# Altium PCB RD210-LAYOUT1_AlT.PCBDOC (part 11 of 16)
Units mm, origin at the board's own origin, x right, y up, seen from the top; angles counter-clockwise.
Board outline 330 x 300 mm, 6 copper layers (TOP, Mid-Layer 1, Mid-Layer 2, Mid-Layer 3, Mid-Layer 4, BOTTOM), stack 1.422 mm thick; 981 components, 463 nets, 2326 pads, 12534 vias.
Unrouted connection lines stored in the file: 6.
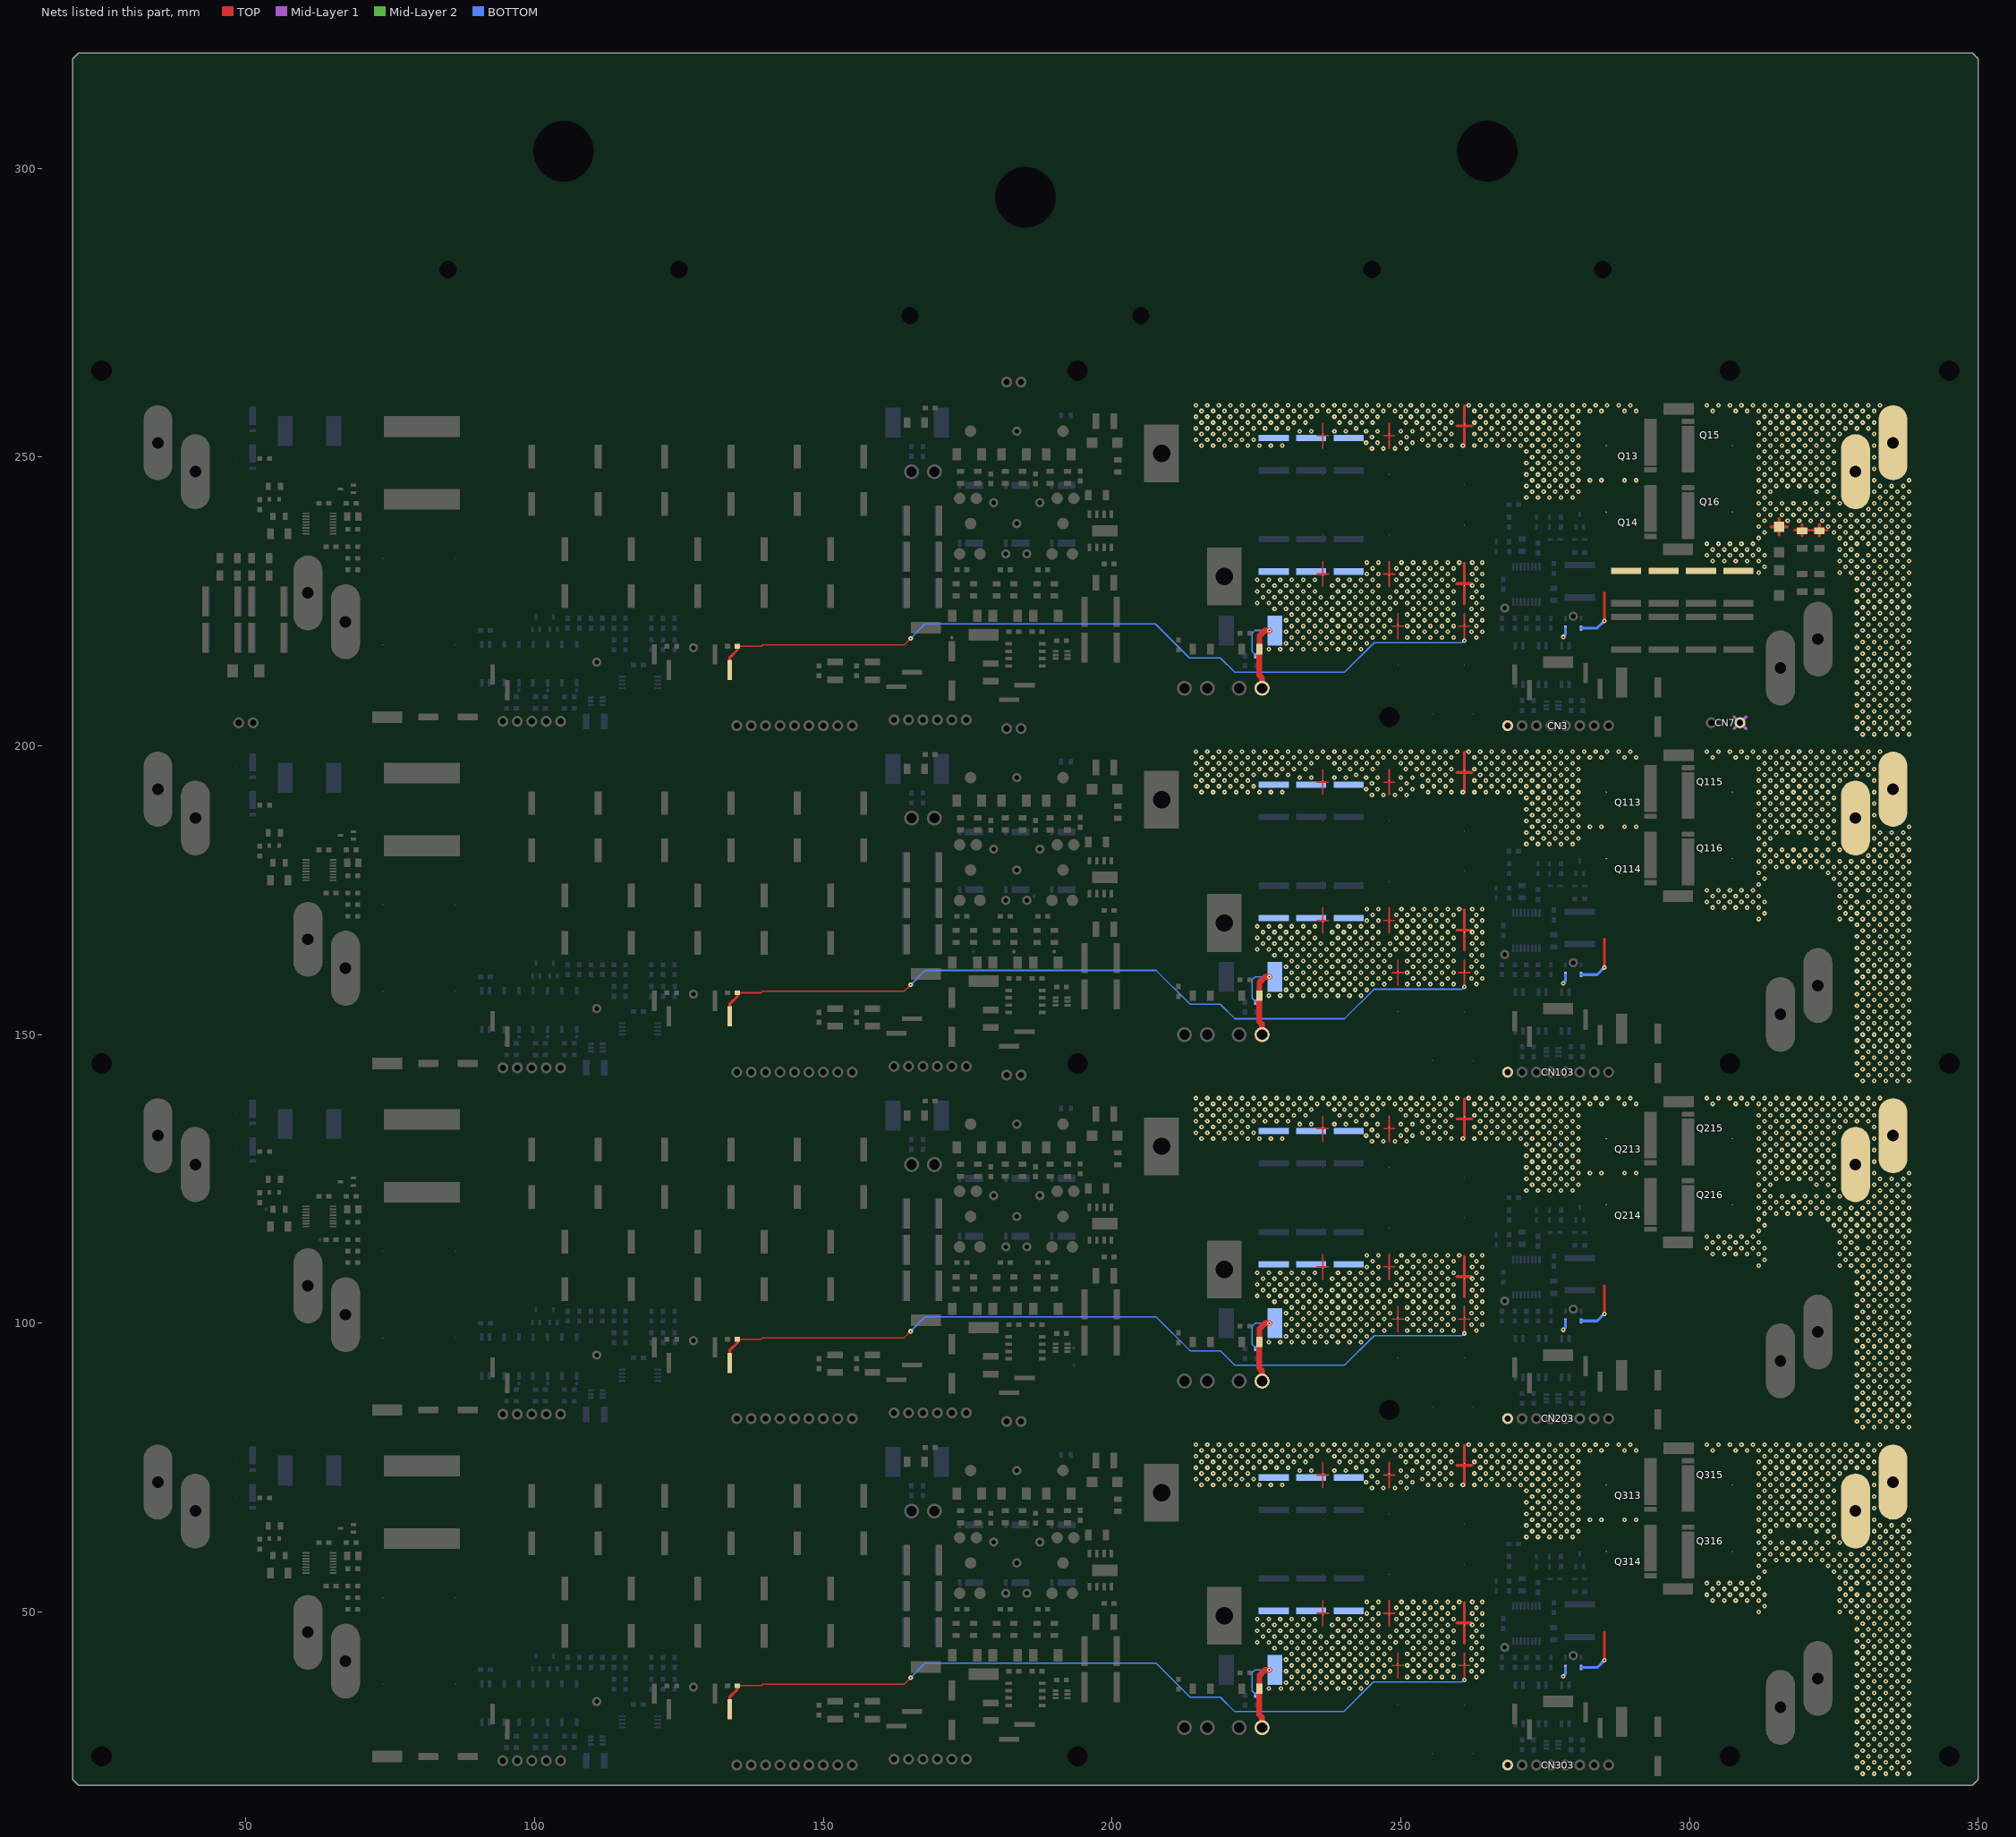
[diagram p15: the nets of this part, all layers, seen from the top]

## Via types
v1: diameter 0.8, hole 0.3, TOP to BOTTOM, 12534 vias

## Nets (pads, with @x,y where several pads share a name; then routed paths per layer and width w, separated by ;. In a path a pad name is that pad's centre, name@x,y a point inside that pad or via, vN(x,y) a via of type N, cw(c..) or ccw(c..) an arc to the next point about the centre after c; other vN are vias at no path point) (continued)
VP_L: C85.2 C87.2 C89.2 C91.2 C93.2 C95.2 CN7.1 D13.1 D15.1 D113.1 D213.1 D313.1 Q15.3 Q16.3 Q115.3 Q116.3 Q215.3 Q216.3 Q315.3 Q316.3 TN13.1 TN13.2 TN23.1 TN23.2 TN33.1 TN33.2 TN43.1 TN43.2 | length 63.9
  TOP w0.5: v1(285.25,41.625) 285.25,46.5 ; v1(285.25,101.625) 285.25,106.5 ; v1(285.25,161.625) 285.25,166.5 ; v1(285.25,221.625) 285.25,226.5 ; 314.1,237.95 D15.1@315.5,237.95 ; 315.5,236.55 D15.1@315.5,237.95 ; 315.5,239.35 D15.1@315.5,237.95 ; 316.9,237.95 D15.1@315.5,237.95 ; 318.2,237.35 C85.2@319.5,237.35 ; 319.5,236.35 C85.2@319.5,237.275 C85.2@319.5,237.35 ; 319.5,238.35 C85.2@319.5,237.35 ; 320.8,237.35 C85.2@319.5,237.35 ; 321.2,237.35 C87.2@322.5,237.35 ; 322.5,236.35 C87.2@322.5,237.275 C87.2@322.5,237.35 ; 322.5,238.35 C87.2@322.5,237.35 ; 323.8,237.35 C87.2@322.5,237.35
  Mid-Layer 1 w0.5: 307.725,202.975 CN7.1@308.75,204 ; 307.725,205.025 CN7.1@308.75,204 ; 309.775,202.975 CN7.1@308.75,204 ; 309.775,205.025 CN7.1@308.75,204
  Mid-Layer 2 w0.5: 307.725,202.975 CN7.1@308.75,204 ; 307.725,205.025 CN7.1@308.75,204 ; 309.775,202.975 CN7.1@308.75,204 ; 309.775,205.025 CN7.1@308.75,204
  BOTTOM w0.5: D313.1@281.25,40.4 284.025,40.4 v1(285.25,41.625) ; D213.1@281.25,100.4 284.025,100.4 v1(285.25,101.625) ; D113.1@281.25,160.4 284.025,160.4 v1(285.25,161.625) ; D13.1@281.25,220.4 284.025,220.4 v1(285.25,221.625)
  other v1: 330,22 332,22 334,22 336,22 338,22 329,23 331,23 333,23 335,23 337,23 330,24 332,24 334,24 336,24 338,24 329,25 331,25 333,25 335,25 337,25 330,26 332,26 334,26 336,26 338,26 329,27 331,27 333,27 335,27 337,27 330,28 332,28 334,28 336,28 338,28 329,29 331,29 333,29 335,29 337,29 330,30 332,30 334,30 336,30 338,30 329,31 331,31 333,31 335,31 337,31 330,32 332,32 334,32 336,32 338,32 329,33 331,33 333,33 335,33 337,33 330,34 332,34 334,34 336,34 338,34 329,35 331,35 333,35 335,35 337,35 330,36 332,36 334,36 336,36 338,36 329,37 331,37 333,37 335,37 337,37 330,38 332,38 334,38 336,38 338,38 329,39 331,39 333,39 335,39 337,39 330,40 332,40 334,40 336,40 338,40 329,41 331,41 333,41 335,41 337,41 330,42 332,42 334,42 336,42 338,42 329,43 331,43 333,43 335,43 337,43 330,44 332,44 334,44 336,44 338,44 329,45 331,45 333,45 335,45 337,45 330,46 332,46 334,46 336,46 338,46 329,47 331,47 333,47 335,47 337,47 330,48 332,48 334,48 336,48 338,48 329,49 331,49 333,49 335,49 337,49 312,50 326,50 328,50 330,50 332,50 334,50 336,50 338,50 313,51 327,51 329,51 331,51 333,51 335,51 337,51 304,52 306,52 308,52 310,52 312,52 326,52 328,52 330,52 332,52 334,52 336,52 338,52 303,53 305,53 307,53 309,53 311,53 313,53 327,53 329,53 331,53 333,53 335,53 337,53 304,54 306,54 308,54 310,54 312,54 326,54 328,54 332,54 334,54 336,54 338,54 303,55 305,55 307,55 309,55 311,55 327,55 329,55 331,55 333,55 335,55 337,55 312,56 326,56 328,56 330,56 332,56 334,56 336,56 338,56 313,57 325,57 327,57 329,57 331,57 333,57 335,57 337,57 312,58 324,58 326,58 328,58 330,58 332,58 334,58 336,58 338,58 313,59 315,59 317,59 319,59 321,59 323,59 325,59 327,59 329,59 331,59 333,59 335,59 337,59 312,60 314,60 316,60 318,60 320,60 322,60 324,60 326,60 328,60 330,60 332,60 334,60 336,60 338,60 313,61 315,61 317,61 319,61 321,61 323,61 331,61 333,61 335,61 337,61 312,62 314,62 316,62 318,62 320,62 322,62 324,62 326,62 332,62 334,62 336,62 338,62 313,63 325,63 333,63 335,63 337,63 312,64 314,64 322,64 324,64 332,64 334,64 336,64 338,64 313,65 315,65 317,65 319,65 321,65 323,65 325,65 333,65 335,65 337,65 312,66 314,66 316,66 318,66 320,66 322,66 324,66 332,66 338,66 313,67 315,67 317,67 319,67 321,67 323,67 325,67 312,68 314,68 316,68 318,68 320,68 322,68 324,68 332,68 313,69 315,69 317,69 319,69 321,69 323,69 325,69 312,70 314,70 316,70 318,70 320,70 322,70 324,70 332,70 313,71 315,71 317,71 319,71 321,71 323,71 325,71 312,72 314,72 316,72 318,72 320,72 322,72 324,72 332,72 313,73 315,73 317,73 319,73 321,73 323,73 325,73 312,74 314,74 316,74 318,74 320,74 322,74 324,74 326,74 332,74 313,75 315,75 317,75 319,75 321,75 323,75 325,75 327,75 329,75 331,75 312,76 314,76 316,76 318,76 320,76 322,76 324,76 326,76 328,76 330,76 332,76 313,77 315,77 317,77 319,77 321,77 323,77 325,77 327,77 329,77 331,77 304,78 308,78 310,78 312,78 314,78 316,78 318,78 320,78 322,78 324,78 326,78 328,78 330,78 332,78 303,79 305,79 307,79 309,79 311,79 313,79 315,79 317,79 319,79 321,79 323,79 325,79 327,79 329,79 331,79 333,79 330,82 332,82 334,82 336,82 338,82 329,83 331,83 333,83 335,83 337,83 330,84 332,84 334,84 336,84 338,84 329,85 331,85 333,85 335,85 337,85 330,86 332,86 334,86 336,86 338,86 329,87 331,87 333,87 335,87 337,87 330,88 332,88 334,88 336,88 338,88 329,89 331,89 333,89 335,89 337,89 330,90 332,90 334,90 336,90 338,90 329,91 331,91 333,91 335,91 337,91 330,92 332,92 334,92 336,92 338,92 329,93 331,93 333,93 335,93 337,93 330,94 332,94 334,94 336,94 338,94 329,95 331,95 333,95 335,95 337,95 330,96 332,96 334,96 336,96 338,96 329,97 331,97 333,97 335,97 337,97 330,98 332,98 334,98 336,98 338,98 329,99 331,99 333,99 335,99 337,99 330,100 332,100 334,100 336,100 338,100 329,101 331,101 333,101 335,101 337,101 330,102 332,102 334,102 336,102 338,102 329,103 331,103 333,103 335,103 337,103 330,104 332,104 334,104 336,104 338,104 329,105 331,105 333,105 335,105 337,105 330,106 332,106 334,106 336,106 338,106 329,107 331,107 333,107 335,107 337,107 330,108 332,108 334,108 336,108 338,108 329,109 331,109 333,109 335,109 337,109 312,110 326,110 328,110 330,110 332,110 334,110 336,110 338,110 313,111 327,111 329,111 331,111 333,111 335,111 337,111 304,112 306,112 308,112 310,112 312,112 326,112 328,112 330,112 332,112 334,112 336,112 338,112 303,113 305,113 307,113 309,113 311,113 313,113 327,113 329,113 331,113 333,113 335,113 337,113 304,114 306,114 308,114 310,114 312,114 326,114 328,114 332,114 334,114 336,114 338,114 303,115 305,115 307,115 309,115 311,115 327,115 329,115 331,115 333,115 335,115 337,115 312,116 326,116 328,116 330,116 332,116 334,116 336,116 338,116 313,117 325,117 327,117 329,117 331,117 333,117 335,117 337,117 312,118 324,118 326,118 328,118 330,118 332,118 334,118 336,118 338,118 313,119 315,119 317,119 319,119 321,119 323,119 325,119 327,119 329,119 331,119 333,119 335,119 337,119 312,120 314,120 316,120 318,120 320,120 322,120 324,120 326,120 328,120 330,120 332,120 334,120 336,120 338,120 313,121 315,121 317,121 319,121 321,121 323,121 331,121 333,121 335,121 337,121 312,122 314,122 316,122 318,122 320,122 322,122 324,122 326,122 332,122 334,122 336,122 338,122 313,123 325,123 333,123 335,123 337,123 312,124 314,124 322,124 324,124 332,124 334,124 336,124 338,124 313,125 315,125 317,125 319,125 321,125 323,125 325,125 333,125 335,125 337,125 312,126 314,126 316,126 318,126 320,126 322,126 324,126 332,126 338,126 313,127 315,127 317,127 319,127 321,127 323,127 325,127 312,128 314,128 316,128 318,128 320,128 322,128 324,128 332,128 313,129 315,129 317,129 319,129 321,129 323,129 325,129 312,130 314,130 316,130 318,130 320,130 322,130 324,130 332,130 313,131 315,131 317,131 319,131 321,131 323,131 325,131 312,132 314,132 316,132 318,132 320,132 322,132 324,132 332,132 313,133 315,133 317,133 319,133 321,133 323,133 325,133 312,134 314,134 316,134 318,134 320,134 322,134 324,134 326,134 332,134 313,135 315,135 317,135 319,135 321,135 323,135 325,135 327,135 329,135 331,135 312,136 314,136 316,136 318,136 320,136 322,136 324,136 326,136 328,136 330,136 332,136 313,137 315,137 317,137 319,137 321,137 323,137 325,137 327,137 329,137 331,137 304,138 308,138 310,138 312,138 314,138 316,138 318,138 320,138 322,138 324,138 326,138 328,138 330,138 332,138 303,139 305,139 307,139 309,139 311,139 313,139 315,139 317,139 319,139 321,139 323,139 325,139 327,139 329,139 331,139 333,139 330,142 332,142 334,142 336,142 338,142 329,143 331,143 333,143 335,143 337,143 330,144 332,144 334,144 336,144 338,144 329,145 331,145 333,145 335,145 337,145 330,146 332,146 334,146 336,146 338,146 329,147 331,147 333,147 335,147 337,147 330,148 332,148 334,148 336,148 338,148 329,149 331,149 333,149 335,149 337,149 330,150 332,150 334,150 336,150 338,150 329,151 331,151 333,151 335,151 337,151 330,152 332,152 334,152 336,152 338,152 329,153 331,153 333,153 335,153 337,153 330,154 332,154 334,154 336,154 338,154 329,155 331,155 333,155 335,155 337,155 330,156 332,156 334,156 336,156 338,156 329,157 331,157 333,157 335,157 337,157 330,158 332,158 334,158 336,158 338,158 329,159 331,159 333,159 335,159 337,159 330,160 332,160 334,160 336,160 338,160 329,161 331,161 333,161 335,161 337,161 330,162 332,162 334,162 336,162 338,162 329,163 331,163 333,163 335,163 337,163 330,164 332,164 334,164 336,164 338,164 329,165 331,165 333,165 335,165 337,165 330,166 332,166 334,166 336,166 338,166 329,167 331,167 333,167 335,167 337,167 330,168 332,168 334,168 336,168 338,168 329,169 331,169 333,169 335,169 337,169 312,170 326,170 328,170 330,170 332,170 334,170 336,170 338,170 313,171 327,171 329,171 331,171 333,171 335,171 337,171 304,172 306,172 308,172 310,172 312,172 326,172 328,172 330,172 332,172 334,172 336,172 338,172 303,173 305,173 307,173 309,173 311,173 313,173 327,173 329,173 331,173 333,173 335,173 337,173 304,174 306,174 308,174 310,174 312,174 326,174 328,174 332,174 334,174 336,174 338,174 303,175 305,175 307,175 309,175 311,175 327,175 329,175 331,175 333,175 335,175 337,175 312,176 326,176 328,176 330,176 332,176 334,176 336,176 338,176 313,177 325,177 327,177 329,177 331,177 333,177 335,177 337,177 312,178 324,178 326,178 328,178 330,178 332,178 334,178 336,178 338,178 313,179 315,179 317,179 319,179 321,179 323,179 325,179 327,179 329,179 331,179 333,179 335,179 337,179 312,180 314,180 316,180 318,180 320,180 322,180 324,180 326,180 328,180 330,180 332,180 334,180 336,180 338,180 313,181 315,181 317,181 319,181 321,181 323,181 331,181 333,181 335,181 337,181 312,182 314,182 316,182 318,182 320,182 322,182 324,182 326,182 332,182 334,182 336,182 338,182 313,183 325,183 333,183 335,183 337,183 312,184 314,184 322,184 324,184 332,184 334,184 336,184 338,184 313,185 315,185 317,185 319,185 321,185 323,185 325,185 333,185 335,185 337,185 312,186 314,186 316,186 318,186 320,186 322,186 324,186 332,186 338,186 313,187 315,187 317,187 319,187 321,187 323,187 325,187 312,188 314,188 316,188 318,188 320,188 322,188 324,188 332,188 313,189 315,189 317,189 319,189 321,189 323,189 325,189 312,190 314,190 316,190 318,190 320,190 322,190 324,190 332,190 313,191 315,191 317,191 319,191 321,191 323,191 325,191 312,192 314,192 316,192 318,192 320,192 322,192 324,192 332,192 313,193 315,193 317,193 319,193 321,193 323,193 325,193 312,194 314,194 316,194 318,194 320,194 322,194 324,194 326,194 332,194 313,195 315,195 317,195 319,195 321,195 323,195 325,195 327,195 329,195 331,195 312,196 314,196 316,196 318,196 320,196 322,196 324,196 326,196 328,196 330,196 332,196 313,197 315,197 317,197 319,197 321,197 323,197 325,197 327,197 329,197 331,197 304,198 308,198 310,198 312,198 314,198 316,198 318,198 320,198 322,198 324,198 326,198 328,198 330,198 332,198 303,199 305,199 307,199 309,199 311,199 313,199 315,199 317,199 319,199 321,199 323,199 325,199 327,199 329,199 331,199 333,199 330,202 332,202 334,202 336,202 338,202 329,203 331,203 333,203 335,203 337,203 330,204 332,204 334,204 336,204 338,204 329,205 331,205 333,205 335,205 337,205 330,206 332,206 334,206 336,206 338,206 329,207 331,207 333,207 335,207 337,207 330,208 332,208 334,208 336,208 338,208 329,209 331,209 333,209 335,209 337,209 330,210 332,210 334,210 336,210 338,210 329,211 331,211 333,211 335,211 337,211 330,212 332,212 334,212 336,212 338,212 329,213 331,213 333,213 335,213 337,213 330,214 332,214 334,214 336,214 338,214 329,215 331,215 333,215 335,215 337,215 330,216 332,216 334,216 336,216 338,216 329,217 331,217 333,217 335,217 337,217 330,218 332,218 334,218 336,218 338,218 329,219 331,219 333,219 335,219 337,219 330,220 332,220 334,220 336,220 338,220 329,221 331,221 333,221 335,221 337,221 330,222 332,222 334,222 336,222 338,222 329,223 331,223 333,223 335,223 337,223 330,224 332,224 334,224 336,224 338,224 329,225 331,225 333,225 335,225 337,225 330,226 332,226 334,226 336,226 338,226 329,227 331,227 333,227 335,227 337,227 330,228 332,228 334,228 336,228 338,228 329,229 331,229 333,229 335,229 337,229 312,230 326,230 328,230 330,230 332,230 334,230 336,230 338,230 313,231 327,231 329,231 331,231 333,231 335,231 337,231 304,232 306,232 308,232 310,232 312,232 326,232 328,232 330,232 332,232 334,232 336,232 338,232 303,233 305,233 307,233 309,233 311,233 313,233 327,233 329,233 331,233 333,233 335,233 337,233 304,234 306,234 308,234 310,234 312,234 326,234 328,234 332,234 334,234 336,234 338,234 303,235 305,235 307,235 309,235 311,235 327,235 329,235 331,235 333,235 335,235 337,235 312,236 326,236 328,236 330,236 332,236 334,236 336,236 338,236 313,237 325,237 327,237 329,237 331,237 333,237 335,237 337,237 312,238 324,238 326,238 328,238 330,238 332,238 334,238 336,238 338,238 313,239 317,239 319,239 321,239 323,239 325,239 327,239 329,239 331,239 333,239 335,239 337,239 312,240 314,240 316,240 318,240 320,240 322,240 324,240 326,240 328,240 330,240 332,240 334,240 336,240 338,240 313,241 315,241 317,241 319,241 321,241 323,241 331,241 333,241 335,241 337,241 312,242 314,242 316,242 318,242 320,242 322,242 324,242 326,242 332,242 334,242 336,242 338,242 313,243 325,243 333,243 335,243 337,243 312,244 314,244 322,244 324,244 332,244 334,244 336,244 338,244 313,245 315,245 317,245 319,245 321,245 323,245 325,245 333,245 335,245 337,245 312,246 314,246 316,246 318,246 320,246 322,246 324,246 332,246 338,246 313,247 315,247 317,247 319,247 321,247 323,247 325,247 312,248 314,248 316,248 318,248 320,248 322,248 324,248 332,248 313,249 315,249 317,249 319,249 321,249 323,249 325,249 312,250 314,250 316,250 318,250 320,250 322,250 324,250 332,250 313,251 315,251 317,251 319,251 321,251 323,251 325,251 312,252 314,252 316,252 318,252 320,252 322,252 324,252 332,252 313,253 315,253 317,253 319,253 321,253 323,253 325,253 312,254 314,254 316,254 318,254 320,254 322,254 324,254 326,254 332,254 313,255 315,255 317,255 319,255 321,255 323,255 325,255 327,255 329,255 331,255 312,256 314,256 316,256 318,256 320,256 322,256 324,256 326,256 328,256 330,256 332,256 313,257 315,257 317,257 319,257 321,257 323,257 325,257 327,257 329,257 331,257 304,258 308,258 310,258 312,258 314,258 316,258 318,258 320,258 322,258 324,258 326,258 328,258 330,258 332,258 303,259 305,259 307,259 309,259 311,259 313,259 315,259 317,259 319,259 321,259 323,259 325,259 327,259 329,259 331,259 333,259
VP_L_0-1: C50.1 C51.1 C52.1 C53.1 C54.1 C55.1 C56.1 C57.1 C58.1 C59.2 C60.2 C61.2 C62.2 C63.2 C64.2 C403.2 CN3.8 CN9.1 CN18.1 D12.1 Q13.3 Q14.3 R38.2 R55.2 | length 216
  TOP w0.25: R55.2@135.1,217.25 139.25,217.25 139.5,217.5 164,217.5 v1(165.125,218.625) ; 235.523,229.775 236.5,229.775 ; 235.523,253.725 236.5,253.725 ; 236.5,227.573 C53.1@236.5,229.5 236.5,229.775 ; 236.5,231.977 236.5,229.775 ; 236.5,251.523 236.5,253.725 ; 236.5,255.927 C51.1@236.5,254 236.5,253.725 ; 237.477,229.775 236.5,229.775 ; 237.477,253.725 236.5,253.725 ; 247.023,229.775 248,229.775 ; 247.023,253.725 248,253.725 ; 248,227.573 C54.1@248,229.5 248,229.775 ; 248,231.977 248,229.775 ; 248,251.523 248,253.725 ; 248,255.927 C52.1@248,254 248,253.725 ; 248.523,220.725 249.5,220.725 ; 248.977,229.775 248,229.775 ; 248.977,253.725 248,253.725 ; 249.5,218.523 249.5,220.725 ; 249.5,222.927 C55.1@249.5,221 249.5,220.725 ; 250.477,220.725 249.5,220.725 ; 260.023,220.725 261,220.725 ; v1(261,218.25) 261,220.725 ; 261,222.927 C56.1@261,221 261,220.725 ; 261.977,220.725 261,220.725
  TOP w0.5: CN18.1@133.77,213.15 133.77,215.27 135.1,216.6 R55.2@135.1,217.25 ; 259.696,228.1 261,228.1 ; 259.696,255.4 261,255.4 ; 261,224.596 C58.1@261,227.75 261,228.1 ; 261,231.604 261,228.1 ; v1@261,251.896 261,255.4 ; 261,258.904 C57.1@261,255.75 261,255.4 ; v1@262.304,228.1 261,228.1 ; 262.304,255.4 261,255.4
  TOP w1: CN9.1@225.98,210 225.98,211.77 225.5,212.25 225.5,216.625 225.525,216.65 C403.2@225.525,216.75 225.525,219.025 226.5,220 v1(227.25,220)
  BOTTOM w0.25: v1(165.125,218.625) 167.625,221.125 207.5,221.125 213.375,215.25 218.75,215.25 221.25,212.75 240.25,212.75 245.375,217.875 260.625,217.875 v1(261,218.25) ; C50.1@225,215.6 224.25,216.35 224.25,219.5 224.75,220 v1(227.25,220)
  BOTTOM w0.5: v1(278.125,218.875) 278.5,219.25 D12.1@278.5,220.4
  other v1: 227.125,216.75 229.125,216.75 231.125,216.75 233.125,216.75 235.125,216.75 237.125,216.75 239.125,216.75 241.125,216.75 243.125,216.75 230.125,217.75 232.125,217.75 234.125,217.75 236.125,217.75 238.125,217.75 240.125,217.75 242.125,217.75 244.125,217.75 231.125,218.75 233.125,218.75 235.125,218.75 237.125,218.75 239.125,218.75 241.125,218.75 243.125,218.75 245.125,218.75 247.125,218.75 251.125,218.75 253.125,218.75 255.125,218.75 257.125,218.75 259.125,218.75 263.125,218.75 230.125,219.75 232.125,219.75 234.125,219.75 236.125,219.75 238.125,219.75 240.125,219.75 242.125,219.75 244.125,219.75 246.125,219.75 248.125,219.75 252.125,219.75 254.125,219.75 256.125,219.75 258.125,219.75 262.25,219.75 264.125,219.75 231.125,220.75 233.125,220.75 235.125,220.75 237.125,220.75 239.125,220.75 241.125,220.75 243.125,220.75 245.125,220.75 247.125,220.75 251.125,220.75 253.125,220.75 255.125,220.75 257.125,220.75 259.125,220.75 263.125,220.75 230.125,221.75 232.125,221.75 234.125,221.75 236.125,221.75 238.125,221.75 240.125,221.75 242.125,221.75 244.125,221.75 246.125,221.75 248.125,221.75 252.125,221.75 254.125,221.75 256.125,221.75 258.125,221.75 262.25,221.75 264.125,221.75 231.125,222.75 233.125,222.75 235.125,222.75 237.125,222.75 239.125,222.75 241.125,222.75 243.125,222.75 245.125,222.75 247.125,222.75 251.125,222.75 253.125,222.75 255.125,222.75 257.125,222.75 259.125,222.75 263.125,222.75 228.125,223.75 230.125,223.75 232.125,223.75 234.125,223.75 236.125,223.75 238.125,223.75 240.125,223.75 242.125,223.75 244.125,223.75 246.125,223.75 248.125,223.75 252.125,223.75 254.125,223.75 256.125,223.75 258.125,223.75 262.25,223.75 264.125,223.75 225.125,224.75 227.125,224.75 229.125,224.75 231.125,224.75 233.125,224.75 235.125,224.75 237.125,224.75 239.125,224.75 241.125,224.75 243.125,224.75 245.125,224.75 247.125,224.75 249.125,224.75 251.125,224.75 253.125,224.75 255.125,224.75 257.125,224.75 259.125,224.75 263.125,224.75 226.125,225.75 228.125,225.75 230.125,225.75 232.125,225.75 234.125,225.75 236.125,225.75 238.125,225.75 240.125,225.75 242.125,225.75 244.125,225.75 246.125,225.75 248.125,225.75 250.125,225.75 252.125,225.75 254.125,225.75 256.125,225.75 258.125,225.75 262.375,225.75 264.125,225.75 225.125,226.75 227.125,226.75 229.125,226.75 231.125,226.75 233.125,226.75 235.125,226.75 239.125,226.75 241.125,226.75 243.125,226.75 245.125,226.75 249.25,226.75 251.125,226.75 253.125,226.75 255.125,226.75 257.125,226.75 259.125,226.75 263.125,226.75 226.125,227.75 228.125,227.75 230.125,227.75 232.125,227.75 234.125,227.75 238.125,227.75 240.125,227.75 242.125,227.75 244.125,227.75 246.125,227.75 250.125,227.75 252.125,227.75 254.125,227.75 256.125,227.75 258.125,227.75 262.375,227.75 264.125,227.75 225.125,228.75 227.125,228.75 229.125,228.75 231.125,228.75 233.125,228.75 235.125,228.75 239.125,228.75 241.125,228.75 243.125,228.75 245.125,228.75 249.25,228.75 251.125,228.75 253.125,228.75 255.125,228.75 257.125,228.75 259.125,228.75 263.125,228.75 244.125,229.75 246.125,229.75 250.125,229.75 252.125,229.75 254.125,229.75 256.125,229.75 258.125,229.75 262.375,229.75 264.125,229.75 245.125,230.75 249.25,230.75 251.125,230.75 253.125,230.75 255.125,230.75 257.125,230.75 259.125,230.75 263.125,230.75 244.125,231.75 246.125,231.75 250.125,231.75 252.125,231.75 254.125,231.75 256.125,231.75 258.125,231.75 260.125,231.75 262.375,231.75 264.125,231.75 271.75,243 273.75,243 275.75,243 277.75,243 279.75,243 272.75,244 274.75,244 276.75,244 278.75,244 280.75,244 271.75,245 273.75,245 275.75,245 277.75,245 279.75,245 272.75,246 274.75,246 276.75,246 278.75,246 280.75,246 282.75,246 284.75,246 288.75,246 290.75,246 271.75,247 273.75,247 275.75,247 277.75,247 279.75,247 272.75,248 274.75,248 276.75,248 278.75,248 280.75,248 271.75,249 273.75,249 275.75,249 277.75,249 279.75,249 272.75,250 274.75,250 276.75,250 278.75,250 280.75,250 271.75,251 273.75,251 275.75,251 277.75,251 279.75,251 245,251.5 247,251.5 249,251.5 251,251.5 215.5,252 217.5,252 219.5,252 221.5,252 223.5,252 225.5,252 227.5,252 229.5,252 254.75,252 256.75,252 258.75,252 260.75,252 262.75,252 264.75,252 266.75,252 268.75,252 270.75,252 272.75,252 274.75,252 276.75,252 278.75,252 280.75,252 244,252.5 246,252.5 250,252.5 252,252.5 214.5,253 216.5,253 218.5,253 220.5,253 222.5,253 224.5,253 253.75,253 255.75,253 257.75,253 263.75,253 265.75,253 267.75,253 269.75,253 271.75,253 273.75,253 275.75,253 277.75,253 279.75,253 245,253.5 251,253.5 215.5,254 217.5,254 219.5,254 221.5,254 223.5,254 254.75,254 256.75,254 258.75,254 262.75,254 264.75,254 266.75,254 268.75,254 270.75,254 272.75,254 274.75,254 276.75,254 278.75,254 280.75,254 232.5,254.5 234.5,254.5 238.5,254.5 240.5,254.5 244,254.5 246,254.5 250,254.5 252,254.5 214.5,255 216.5,255 218.5,255 220.5,255 222.5,255 224.5,255 226.5,255 228.5,255 230.5,255 242.25,255 253.75,255 255.75,255 257.75,255 263.75,255 265.75,255 267.75,255 269.75,255 271.75,255 273.75,255 275.75,255 277.75,255 279.75,255 215.5,256 217.5,256 219.5,256 221.5,256 223.5,256 225.5,256 227.5,256 229.5,256 231.5,256 233.5,256 239.375,256 241.25,256 243.25,256 245.125,256 250.875,256 252.75,256 254.75,256 256.75,256 258.75,256 262.75,256 264.75,256 266.75,256 268.75,256 270.75,256 272.75,256 274.75,256 276.75,256 278.75,256 280.75,256 214.5,257 216.5,257 218.5,257 220.5,257 222.5,257 224.5,257 226.5,257 228.5,257 230.5,257 232.5,257 234.5,257 238.5,257 240.25,257 242.25,257 244.125,257 246,257 250,257 251.75,257 253.75,257 255.75,257 257.75,257 263.75,257 265.75,257 267.75,257 269.75,257 271.75,257 273.75,257 275.75,257 277.75,257 279.75,257 215.5,258 217.5,258 219.5,258 221.5,258 223.5,258 225.5,258 227.5,258 229.5,258 231.5,258 233.5,258 235.5,258 237.5,258 239.375,258 241.25,258 243.25,258 245.125,258 247,258 249,258 250.875,258 252.75,258 254.75,258 256.75,258 258.75,258 262.75,258 264.75,258 266.75,258 268.75,258 270.75,258 272.75,258 274.75,258 276.75,258 278.75,258 280.75,258 282.75,258 284.75,258 288.75,258 290.75,258 214.5,259 216.5,259 218.5,259 220.5,259 222.5,259 224.5,259 226.5,259 228.5,259 230.5,259 232.5,259 234.5,259 236.5,259 238.5,259 240.25,259 242.25,259 244.125,259 246.125,259 248,259 250,259 251.75,259 253.75,259 255.75,259 257.75,259 259.75,259 261.75,259 263.75,259 265.75,259 267.75,259 269.75,259 271.75,259 273.75,259 275.75,259 277.75,259 279.75,259 281.75,259 283.75,259 285.75,259 287.75,259 289.75,259
VP_L_0-2: C150.1 C151.1 C152.1 C153.1 C154.1 C155.1 C156.1 C157.1 C158.1 C159.2 C160.2 C161.2 C162.2 C163.2 C164.2 C413.2 CN103.8 CN109.1 CN118.1 D112.1 Q113.3 Q114.3 R138.2 R155.2 | length 216
  TOP w0.25: R155.2@135.1,157.25 139.25,157.25 139.5,157.5 164,157.5 v1(165.125,158.625) ; 235.523,169.775 236.5,169.775 ; 235.523,193.725 236.5,193.725 ; 236.5,167.573 C153.1@236.5,169.5 236.5,169.775 ; 236.5,171.977 236.5,169.775 ; 236.5,191.523 236.5,193.725 ; 236.5,195.927 C151.1@236.5,194 236.5,193.725 ; 237.477,169.775 236.5,169.775 ; 237.477,193.725 236.5,193.725 ; 247.023,169.775 248,169.775 ; 247.023,193.725 248,193.725 ; 248,167.573 C154.1@248,169.5 248,169.775 ; 248,171.977 248,169.775 ; 248,191.523 248,193.725 ; 248,195.927 C152.1@248,194 248,193.725 ; 248.523,160.725 249.5,160.725 ; 248.977,169.775 248,169.775 ; 248.977,193.725 248,193.725 ; 249.5,158.523 249.5,160.725 ; 249.5,162.927 C155.1@249.5,161 249.5,160.725 ; 250.477,160.725 249.5,160.725 ; 260.023,160.725 261,160.725 ; v1(261,158.25) 261,160.725 ; 261,162.927 C156.1@261,161 261,160.725 ; 261.977,160.725 261,160.725
  TOP w0.5: CN118.1@133.77,153.15 133.77,155.27 135.1,156.6 R155.2@135.1,157.25 ; 259.696,168.1 261,168.1 ; 259.696,195.4 261,195.4 ; 261,164.596 C158.1@261,167.75 261,168.1 ; 261,171.604 261,168.1 ; v1@261,191.896 261,195.4 ; 261,198.904 C157.1@261,195.75 261,195.4 ; v1@262.304,168.1 261,168.1 ; 262.304,195.4 261,195.4
  TOP w1: CN109.1@225.98,150 225.98,151.77 225.5,152.25 225.5,156.625 225.525,156.65 C413.2@225.525,156.75 225.525,159.025 226.5,160 v1(227.25,160)
  BOTTOM w0.25: v1(165.125,158.625) 167.625,161.125 207.625,161.125 213.5,155.25 218.75,155.25 221.25,152.75 240.25,152.75 245.375,157.875 260.625,157.875 v1(261,158.25) ; C150.1@225,155.6 224.25,156.35 224.25,159.5 224.75,160 v1(227.25,160)
  BOTTOM w0.5: v1(278.125,158.875) 278.5,159.25 D112.1@278.5,160.4
  other v1: 227.125,156.75 229.125,156.75 231.125,156.75 233.125,156.75 235.125,156.75 237.125,156.75 239.125,156.75 241.125,156.75 243.125,156.75 230.125,157.75 232.125,157.75 234.125,157.75 236.125,157.75 238.125,157.75 240.125,157.75 242.125,157.75 244.125,157.75 231.125,158.75 233.125,158.75 235.125,158.75 237.125,158.75 239.125,158.75 241.125,158.75 243.125,158.75 245.125,158.75 247.125,158.75 251.125,158.75 253.125,158.75 255.125,158.75 257.125,158.75 259.125,158.75 263.125,158.75 230.125,159.75 232.125,159.75 234.125,159.75 236.125,159.75 238.125,159.75 240.125,159.75 242.125,159.75 244.125,159.75 246.125,159.75 248.125,159.75 252.125,159.75 254.125,159.75 256.125,159.75 258.125,159.75 262.25,159.75 264.125,159.75 231.125,160.75 233.125,160.75 235.125,160.75 237.125,160.75 239.125,160.75 241.125,160.75 243.125,160.75 245.125,160.75 247.125,160.75 251.125,160.75 253.125,160.75 255.125,160.75 257.125,160.75 259.125,160.75 263.125,160.75 230.125,161.75 232.125,161.75 234.125,161.75 236.125,161.75 238.125,161.75 240.125,161.75 242.125,161.75 244.125,161.75 246.125,161.75 248.125,161.75 252.125,161.75 254.125,161.75 256.125,161.75 258.125,161.75 262.25,161.75 264.125,161.75 231.125,162.75 233.125,162.75 235.125,162.75 237.125,162.75 239.125,162.75 241.125,162.75 243.125,162.75 245.125,162.75 247.125,162.75 251.125,162.75 253.125,162.75 255.125,162.75 257.125,162.75 259.125,162.75 263.125,162.75 228.125,163.75 230.125,163.75 232.125,163.75 234.125,163.75 236.125,163.75 238.125,163.75 240.125,163.75 242.125,163.75 244.125,163.75 246.125,163.75 248.125,163.75 252.125,163.75 254.125,163.75 256.125,163.75 258.125,163.75 262.25,163.75 264.125,163.75 225.125,164.75 227.125,164.75 229.125,164.75 231.125,164.75 233.125,164.75 235.125,164.75 237.125,164.75 239.125,164.75 241.125,164.75 243.125,164.75 245.125,164.75 247.125,164.75 249.125,164.75 251.125,164.75 253.125,164.75 255.125,164.75 257.125,164.75 259.125,164.75 263.125,164.75 226.125,165.75 228.125,165.75 230.125,165.75 232.125,165.75 234.125,165.75 236.125,165.75 238.125,165.75 240.125,165.75 242.125,165.75 244.125,165.75 246.125,165.75 248.125,165.75 250.125,165.75 252.125,165.75 254.125,165.75 256.125,165.75 258.125,165.75 262.375,165.75 264.125,165.75 225.125,166.75 227.125,166.75 229.125,166.75 231.125,166.75 233.125,166.75 235.125,166.75 239.125,166.75 241.125,166.75 243.125,166.75 245.125,166.75 249.25,166.75 251.125,166.75 253.125,166.75 255.125,166.75 257.125,166.75 259.125,166.75 263.125,166.75 226.125,167.75 228.125,167.75 230.125,167.75 232.125,167.75 234.125,167.75 238.125,167.75 240.125,167.75 242.125,167.75 244.125,167.75 246.125,167.75 250.125,167.75 252.125,167.75 254.125,167.75 256.125,167.75 258.125,167.75 262.375,167.75 264.125,167.75 225.125,168.75 227.125,168.75 229.125,168.75 231.125,168.75 233.125,168.75 235.125,168.75 239.125,168.75 241.125,168.75 243.125,168.75 245.125,168.75 249.25,168.75 251.125,168.75 253.125,168.75 255.125,168.75 257.125,168.75 259.125,168.75 263.125,168.75 244.125,169.75 246.125,169.75 250.125,169.75 252.125,169.75 254.125,169.75 256.125,169.75 258.125,169.75 262.375,169.75 264.125,169.75 245.125,170.75 249.25,170.75 251.125,170.75 253.125,170.75 255.125,170.75 257.125,170.75 259.125,170.75 263.125,170.75 244.125,171.75 246.125,171.75 250.125,171.75 252.125,171.75 254.125,171.75 256.125,171.75 258.125,171.75 260.125,171.75 262.375,171.75 264.125,171.75 271.75,183 273.75,183 275.75,183 277.75,183 279.75,183 272.75,184 274.75,184 276.75,184 278.75,184 280.75,184 271.75,185 273.75,185 275.75,185 277.75,185 279.75,185 272.75,186 274.75,186 276.75,186 278.75,186 280.75,186 282.75,186 284.75,186 288.75,186 290.75,186 271.75,187 273.75,187 275.75,187 277.75,187 279.75,187 272.75,188 274.75,188 276.75,188 278.75,188 280.75,188 271.75,189 273.75,189 275.75,189 277.75,189 279.75,189 272.75,190 274.75,190 276.75,190 278.75,190 280.75,190 271.75,191 273.75,191 275.75,191 277.75,191 279.75,191 245,191.5 247,191.5 249,191.5 251,191.5 215.5,192 217.5,192 219.5,192 221.5,192 223.5,192 225.5,192 227.5,192 229.5,192 254.75,192 256.75,192 258.75,192 260.75,192 262.75,192 264.75,192 266.75,192 268.75,192 270.75,192 272.75,192 274.75,192 276.75,192 278.75,192 280.75,192 244,192.5 246,192.5 250,192.5 252,192.5 214.5,193 216.5,193 218.5,193 220.5,193 222.5,193 224.5,193 253.75,193 255.75,193 257.75,193 263.75,193 265.75,193 267.75,193 269.75,193 271.75,193 273.75,193 275.75,193 277.75,193 279.75,193 245,193.5 251,193.5 215.5,194 217.5,194 219.5,194 221.5,194 223.5,194 254.75,194 256.75,194 258.75,194 262.75,194 264.75,194 266.75,194 268.75,194 270.75,194 272.75,194 274.75,194 276.75,194 278.75,194 280.75,194 232.5,194.5 234.5,194.5 238.5,194.5 240.5,194.5 244,194.5 246,194.5 250,194.5 252,194.5 214.5,195 216.5,195 218.5,195 220.5,195 222.5,195 224.5,195 226.5,195 228.5,195 230.5,195 242.25,195 253.75,195 255.75,195 257.75,195 263.75,195 265.75,195 267.75,195 269.75,195 271.75,195 273.75,195 275.75,195 277.75,195 279.75,195 215.5,196 217.5,196 219.5,196 221.5,196 223.5,196 225.5,196 227.5,196 229.5,196 231.5,196 233.5,196 239.375,196 241.25,196 243.25,196 245.125,196 250.875,196 252.75,196 254.75,196 256.75,196 258.75,196 262.75,196 264.75,196 266.75,196 268.75,196 270.75,196 272.75,196 274.75,196 276.75,196 278.75,196 280.75,196 214.5,197 216.5,197 218.5,197 220.5,197 222.5,197 224.5,197 226.5,197 228.5,197 230.5,197 232.5,197 234.5,197 238.5,197 240.25,197 242.25,197 244.125,197 246,197 250,197 251.75,197 253.75,197 255.75,197 257.75,197 263.75,197 265.75,197 267.75,197 269.75,197 271.75,197 273.75,197 275.75,197 277.75,197 279.75,197 215.5,198 217.5,198 219.5,198 221.5,198 223.5,198 225.5,198 227.5,198 229.5,198 231.5,198 233.5,198 235.5,198 237.5,198 239.375,198 241.25,198 243.25,198 245.125,198 247,198 249,198 250.875,198 252.75,198 254.75,198 256.75,198 258.75,198 262.75,198 264.75,198 266.75,198 268.75,198 270.75,198 272.75,198 274.75,198 276.75,198 278.75,198 280.75,198 282.75,198 284.75,198 288.75,198 290.75,198 214.5,199 216.5,199 218.5,199 220.5,199 222.5,199 224.5,199 226.5,199 228.5,199 230.5,199 232.5,199 234.5,199 236.5,199 238.5,199 240.25,199 242.25,199 244.125,199 246.125,199 248,199 250,199 251.75,199 253.75,199 255.75,199 257.75,199 259.75,199 261.75,199 263.75,199 265.75,199 267.75,199 269.75,199 271.75,199 273.75,199 275.75,199 277.75,199 279.75,199 281.75,199 283.75,199 285.75,199 287.75,199 289.75,199
VP_L_0-3: C250.1 C251.1 C252.1 C253.1 C254.1 C255.1 C256.1 C257.1 C258.1 C259.2 C260.2 C261.2 C262.2 C263.2 C264.2 C423.2 CN203.8 CN209.1 CN218.1 D212.1 Q213.3 Q214.3 R238.2 R255.2 | length 216
  TOP w0.25: R255.2@135.1,97.25 139.25,97.25 139.5,97.5 164,97.5 v1(165.125,98.625) ; 235.523,109.775 236.5,109.775 ; 235.523,133.725 236.5,133.725 ; 236.5,107.573 C253.1@236.5,109.5 236.5,109.775 ; 236.5,111.977 236.5,109.775 ; 236.5,131.523 236.5,133.725 ; 236.5,135.927 C251.1@236.5,134 236.5,133.725 ; 237.477,109.775 236.5,109.775 ; 237.477,133.725 236.5,133.725 ; 247.023,109.775 248,109.775 ; 247.023,133.725 248,133.725 ; 248,107.573 C254.1@248,109.5 248,109.775 ; 248,111.977 248,109.775 ; 248,131.523 248,133.725 ; 248,135.927 C252.1@248,134 248,133.725 ; 248.523,100.725 249.5,100.725 ; 248.977,109.775 248,109.775 ; 248.977,133.725 248,133.725 ; 249.5,98.523 249.5,100.725 ; 249.5,102.927 C256.1@249.5,101 249.5,100.725 ; 250.477,100.725 249.5,100.725 ; 260.023,100.725 261,100.725 ; v1(261,98.25) 261,100.725 ; 261,102.927 C255.1@261,101 261,100.725 ; 261.977,100.725 261,100.725
  TOP w0.5: CN218.1@133.77,93.15 133.77,95.27 135.1,96.6 R255.2@135.1,97.25 ; 259.696,108.1 261,108.1 ; 259.696,135.4 261,135.4 ; 261,104.596 C258.1@261,107.75 261,108.1 ; 261,111.604 261,108.1 ; v1@261,131.896 261,135.4 ; 261,138.904 C257.1@261,135.75 261,135.4 ; v1@262.304,108.1 261,108.1 ; 262.304,135.4 261,135.4
  TOP w1: CN209.1@225.98,90 225.98,91.77 225.5,92.25 225.5,96.625 225.525,96.65 C423.2@225.525,96.75 225.525,99.025 226.5,100 v1(227.25,100)
  BOTTOM w0.25: v1(165.125,98.625) 167.625,101.125 207.625,101.125 213.5,95.25 218.75,95.25 221.25,92.75 240.25,92.75 245.375,97.875 260.625,97.875 v1(261,98.25) ; C250.1@225,95.6 224.25,96.35 224.25,99.5 224.75,100 v1(227.25,100)
  BOTTOM w0.5: v1(278.125,98.875) 278.5,99.25 D212.1@278.5,100.4
  other v1: 227.125,96.75 229.125,96.75 231.125,96.75 233.125,96.75 235.125,96.75 237.125,96.75 239.125,96.75 241.125,96.75 243.125,96.75 230.125,97.75 232.125,97.75 234.125,97.75 236.125,97.75 238.125,97.75 240.125,97.75 242.125,97.75 244.125,97.75 231.125,98.75 233.125,98.75 235.125,98.75 237.125,98.75 239.125,98.75 241.125,98.75 243.125,98.75 245.125,98.75 247.125,98.75 251.125,98.75 253.125,98.75 255.125,98.75 257.125,98.75 259.125,98.75 263.125,98.75 230.125,99.75 232.125,99.75 234.125,99.75 236.125,99.75 238.125,99.75 240.125,99.75 242.125,99.75 244.125,99.75 246.125,99.75 248.125,99.75 252.125,99.75 254.125,99.75 256.125,99.75 258.125,99.75 262.25,99.75 264.125,99.75 231.125,100.75 233.125,100.75 235.125,100.75 237.125,100.75 239.125,100.75 241.125,100.75 243.125,100.75 245.125,100.75 247.125,100.75 251.125,100.75 253.125,100.75 255.125,100.75 257.125,100.75 259.125,100.75 263.125,100.75 230.125,101.75 232.125,101.75 234.125,101.75 236.125,101.75 238.125,101.75 240.125,101.75 242.125,101.75 244.125,101.75 246.125,101.75 248.125,101.75 252.125,101.75 254.125,101.75 256.125,101.75 258.125,101.75 262.25,101.75 264.125,101.75 231.125,102.75 233.125,102.75 235.125,102.75 237.125,102.75 239.125,102.75 241.125,102.75 243.125,102.75 245.125,102.75 247.125,102.75 251.125,102.75 253.125,102.75 255.125,102.75 257.125,102.75 259.125,102.75 263.125,102.75 228.125,103.75 230.125,103.75 232.125,103.75 234.125,103.75 236.125,103.75 238.125,103.75 240.125,103.75 242.125,103.75 244.125,103.75 246.125,103.75 248.125,103.75 252.125,103.75 254.125,103.75 256.125,103.75 258.125,103.75 262.25,103.75 264.125,103.75 225.125,104.75 227.125,104.75 229.125,104.75 231.125,104.75 233.125,104.75 235.125,104.75 237.125,104.75 239.125,104.75 241.125,104.75 243.125,104.75 245.125,104.75 247.125,104.75 249.125,104.75 251.125,104.75 253.125,104.75 255.125,104.75 257.125,104.75 259.125,104.75 263.125,104.75 226.125,105.75 228.125,105.75 230.125,105.75 232.125,105.75 234.125,105.75 236.125,105.75 238.125,105.75 240.125,105.75 242.125,105.75 244.125,105.75 246.125,105.75 248.125,105.75 250.125,105.75 252.125,105.75 254.125,105.75 256.125,105.75 258.125,105.75 262.375,105.75 264.125,105.75 225.125,106.75 227.125,106.75 229.125,106.75 231.125,106.75 233.125,106.75 235.125,106.75 239.125,106.75 241.125,106.75 243.125,106.75 245.125,106.75 249.25,106.75 251.125,106.75 253.125,106.75 255.125,106.75 257.125,106.75 259.125,106.75 263.125,106.75 226.125,107.75 228.125,107.75 230.125,107.75 232.125,107.75 234.125,107.75 238.125,107.75 240.125,107.75 242.125,107.75 244.125,107.75 246.125,107.75 250.125,107.75 252.125,107.75 254.125,107.75 256.125,107.75 258.125,107.75 262.375,107.75 264.125,107.75 225.125,108.75 227.125,108.75 229.125,108.75 231.125,108.75 233.125,108.75 235.125,108.75 239.125,108.75 241.125,108.75 243.125,108.75 245.125,108.75 249.25,108.75 251.125,108.75 253.125,108.75 255.125,108.75 257.125,108.75 259.125,108.75 263.125,108.75 244.125,109.75 246.125,109.75 250.125,109.75 252.125,109.75 254.125,109.75 256.125,109.75 258.125,109.75 262.375,109.75 264.125,109.75 245.125,110.75 249.25,110.75 251.125,110.75 253.125,110.75 255.125,110.75 257.125,110.75 259.125,110.75 263.125,110.75 244.125,111.75 246.125,111.75 250.125,111.75 252.125,111.75 254.125,111.75 256.125,111.75 258.125,111.75 260.125,111.75 262.375,111.75 264.125,111.75 271.75,123 273.75,123 275.75,123 277.75,123 279.75,123 272.75,124 274.75,124 276.75,124 278.75,124 280.75,124 271.75,125 273.75,125 275.75,125 277.75,125 279.75,125 272.75,126 274.75,126 276.75,126 278.75,126 280.75,126 282.75,126 284.75,126 288.75,126 290.75,126 271.75,127 273.75,127 275.75,127 277.75,127 279.75,127 272.75,128 274.75,128 276.75,128 278.75,128 280.75,128 271.75,129 273.75,129 275.75,129 277.75,129 279.75,129 272.75,130 274.75,130 276.75,130 278.75,130 280.75,130 271.75,131 273.75,131 275.75,131 277.75,131 279.75,131 245,131.5 247,131.5 249,131.5 251,131.5 215.5,132 217.5,132 219.5,132 221.5,132 223.5,132 225.5,132 227.5,132 229.5,132 254.75,132 256.75,132 258.75,132 260.75,132 262.75,132 264.75,132 266.75,132 268.75,132 270.75,132 272.75,132 274.75,132 276.75,132 278.75,132 280.75,132 244,132.5 246,132.5 250,132.5 252,132.5 214.5,133 216.5,133 218.5,133 220.5,133 222.5,133 224.5,133 253.75,133 255.75,133 257.75,133 263.75,133 265.75,133 267.75,133 269.75,133 271.75,133 273.75,133 275.75,133 277.75,133 279.75,133 245,133.5 251,133.5 215.5,134 217.5,134 219.5,134 221.5,134 223.5,134 254.75,134 256.75,134 258.75,134 262.75,134 264.75,134 266.75,134 268.75,134 270.75,134 272.75,134 274.75,134 276.75,134 278.75,134 280.75,134 232.5,134.5 234.5,134.5 238.5,134.5 240.5,134.5 244,134.5 246,134.5 250,134.5 252,134.5 214.5,135 216.5,135 218.5,135 220.5,135 222.5,135 224.5,135 226.5,135 228.5,135 230.5,135 242.25,135 253.75,135 255.75,135 257.75,135 263.75,135 265.75,135 267.75,135 269.75,135 271.75,135 273.75,135 275.75,135 277.75,135 279.75,135 215.5,136 217.5,136 219.5,136 221.5,136 223.5,136 225.5,136 227.5,136 229.5,136 231.5,136 233.5,136 239.375,136 241.25,136 243.25,136 245.125,136 250.875,136 252.75,136 254.75,136 256.75,136 258.75,136 262.75,136 264.75,136 266.75,136 268.75,136 270.75,136 272.75,136 274.75,136 276.75,136 278.75,136 280.75,136 214.5,137 216.5,137 218.5,137 220.5,137 222.5,137 224.5,137 226.5,137 228.5,137 230.5,137 232.5,137 234.5,137 238.5,137 240.25,137 242.25,137 244.125,137 246,137 250,137 251.75,137 253.75,137 255.75,137 257.75,137 263.75,137 265.75,137 267.75,137 269.75,137 271.75,137 273.75,137 275.75,137 277.75,137 279.75,137 215.5,138 217.5,138 219.5,138 221.5,138 223.5,138 225.5,138 227.5,138 229.5,138 231.5,138 233.5,138 235.5,138 237.5,138 239.375,138 241.25,138 243.25,138 245.125,138 247,138 249,138 250.875,138 252.75,138 254.75,138 256.75,138 258.75,138 262.75,138 264.75,138 266.75,138 268.75,138 270.75,138 272.75,138 274.75,138 276.75,138 278.75,138 280.75,138 282.75,138 284.75,138 288.75,138 290.75,138 214.5,139 216.5,139 218.5,139 220.5,139 222.5,139 224.5,139 226.5,139 228.5,139 230.5,139 232.5,139 234.5,139 236.5,139 238.5,139 240.25,139 242.25,139 244.125,139 246.125,139 248,139 250,139 251.75,139 253.75,139 255.75,139 257.75,139 259.75,139 261.75,139 263.75,139 265.75,139 267.75,139 269.75,139 271.75,139 273.75,139 275.75,139 277.75,139 279.75,139 281.75,139 283.75,139 285.75,139 287.75,139 289.75,139
VP_L_0-4: C350.1 C351.1 C352.1 C353.1 C354.1 C355.1 C356.1 C357.1 C358.1 C359.2 C360.2 C361.2 C362.2 C363.2 C364.2 C433.2 CN303.8 CN309.1 CN318.1 D312.1 Q313.3 Q314.3 R338.2 R355.2 | length 216.1
  TOP w0.25: R355.2@135.1,37.25 139.25,37.25 139.5,37.5 164,37.5 v1(165.125,38.625) ; 235.523,49.775 236.5,49.775 ; 235.523,73.725 236.5,73.725 ; 236.5,47.573 C353.1@236.5,49.5 236.5,49.775 ; 236.5,51.977 236.5,49.775 ; 236.5,71.523 236.5,73.725 ; 236.5,75.927 C351.1@236.5,74 236.5,73.725 ; 237.477,49.775 236.5,49.775 ; 237.477,73.725 236.5,73.725 ; 247.023,49.775 248,49.775 ; 247.023,73.725 248,73.725 ; 248,47.573 C354.1@248,49.5 248,49.775 ; 248,51.977 248,49.775 ; 248,71.523 248,73.725 ; 248,75.927 C352.1@248,74 248,73.725 ; 248.523,40.725 249.5,40.725 ; 248.977,49.775 248,49.775 ; 248.977,73.725 248,73.725 ; 249.5,38.523 249.5,40.725 ; 249.5,42.927 C355.1@249.5,41 249.5,40.725 ; 250.477,40.725 249.5,40.725 ; 260.023,40.725 261,40.725 ; v1(261,38.25) 261,40.725 ; 261,42.927 C356.1@261,41 261,40.725 ; 261.977,40.725 261,40.725
  TOP w0.5: CN318.1@133.77,33.15 133.77,35.27 135.1,36.6 R355.2@135.1,37.25 ; 259.696,48.1 261,48.1 ; 259.696,75.4 261,75.4 ; 261,44.596 C358.1@261,47.75 261,48.1 ; 261,51.604 261,48.1 ; v1@261,71.896 261,75.4 ; 261,78.904 C357.1@261,75.75 261,75.4 ; v1@262.304,48.1 261,48.1 ; 262.304,75.4 261,75.4
  TOP w1: CN309.1@225.98,30 225.98,31.77 225.5,32.25 225.5,36.625 225.525,36.65 C433.2@225.525,36.75 225.525,39.025 226.5,40 v1(227.25,40) ; CN303.8@268.375,23.5 CN303.8@268.5,23.5
  BOTTOM w0.25: v1(165.125,38.625) 167.625,41.125 207.625,41.125 213.5,35.25 218.75,35.25 221.25,32.75 240.125,32.75 245.25,37.875 260.625,37.875 v1(261,38.25) ; C350.1@225,35.6 224.25,36.35 224.25,39.5 224.75,40 v1(227.25,40)
  BOTTOM w0.5: v1(278.125,38.875) 278.5,39.25 D312.1@278.5,40.4
  other v1: 227.125,36.75 229.25,36.75 231.125,36.75 233.125,36.75 235.125,36.75 237.125,36.75 239.125,36.75 241.125,36.75 243.125,36.75 230.125,37.75 232.125,37.75 234.125,37.75 236.125,37.75 238.125,37.75 240.125,37.75 242.125,37.75 244.125,37.75 231.125,38.75 233.125,38.75 235.125,38.75 237.125,38.75 239.125,38.75 241.125,38.75 243.125,38.75 245.125,38.75 247.125,38.75 251.125,38.75 253.125,38.75 255.125,38.75 257.125,38.75 259.125,38.75 263.125,38.75 230.125,39.75 232.125,39.75 234.125,39.75 236.125,39.75 238.125,39.75 240.125,39.75 242.125,39.75 244.125,39.75 246.125,39.75 248.125,39.75 252.125,39.75 254.125,39.75 256.125,39.75 258.125,39.75 262.25,39.75 264.125,39.75 231.125,40.75 233.125,40.75 235.125,40.75 237.125,40.75 239.125,40.75 241.125,40.75 243.125,40.75 245.125,40.75 247.125,40.75 251.125,40.75 253.125,40.75 255.125,40.75 257.125,40.75 259.125,40.75 263.125,40.75 230.125,41.75 232.125,41.75 234.125,41.75 236.125,41.75 238.125,41.75 240.125,41.75 242.125,41.75 244.125,41.75 246.125,41.75 248.125,41.75 252.125,41.75 254.125,41.75 256.125,41.75 258.125,41.75 262.25,41.75 264.125,41.75 231.125,42.75 233.125,42.75 235.125,42.75 237.125,42.75 239.125,42.75 241.125,42.75 243.125,42.75 245.125,42.75 247.125,42.75 251.125,42.75 253.125,42.75 255.125,42.75 257.125,42.75 259.125,42.75 263.125,42.75 228.125,43.75 230.125,43.75 232.125,43.75 234.125,43.75 236.125,43.75 238.125,43.75 240.125,43.75 242.125,43.75 244.125,43.75 246.125,43.75 248.125,43.75 252.125,43.75 254.125,43.75 256.125,43.75 258.125,43.75 262.25,43.75 264.125,43.75 225.125,44.75 227.125,44.75 229.125,44.75 231.125,44.75 233.125,44.75 235.125,44.75 237.125,44.75 239.125,44.75 241.125,44.75 243.125,44.75 245.125,44.75 247.125,44.75 249.125,44.75 251.125,44.75 253.125,44.75 255.125,44.75 257.125,44.75 259.125,44.75 263.125,44.75 226.125,45.75 228.125,45.75 230.125,45.75 232.125,45.75 234.125,45.75 236.125,45.75 238.125,45.75 240.125,45.75 242.125,45.75 244.125,45.75 246.125,45.75 248.125,45.75 250.125,45.75 252.125,45.75 254.125,45.75 256.125,45.75 258.125,45.75 262.375,45.75 264.125,45.75 225.125,46.75 227.125,46.75 229.125,46.75 231.125,46.75 233.125,46.75 235.125,46.75 239.125,46.75 241.125,46.75 243.125,46.75 245.125,46.75 249.25,46.75 251.125,46.75 253.125,46.75 255.125,46.75 257.125,46.75 259.125,46.75 263.125,46.75 226.125,47.75 228.125,47.75 230.125,47.75 232.125,47.75 234.125,47.75 238.125,47.75 240.125,47.75 242.125,47.75 244.125,47.75 246.125,47.75 250.125,47.75 252.125,47.75 254.125,47.75 256.125,47.75 258.125,47.75 262.375,47.75 264.125,47.75 225.125,48.75 227.125,48.75 229.125,48.75 231.125,48.75 233.125,48.75 235.125,48.75 239.125,48.75 241.125,48.75 243.125,48.75 245.125,48.75 249.25,48.75 251.125,48.75 253.125,48.75 255.125,48.75 257.125,48.75 259.125,48.75 263.125,48.75 244.125,49.75 246.125,49.75 250.125,49.75 252.125,49.75 254.125,49.75 256.125,49.75 258.125,49.75 262.375,49.75 264.125,49.75 245.125,50.75 249.25,50.75 251.125,50.75 253.125,50.75 255.125,50.75 257.125,50.75 259.125,50.75 263.125,50.75 244.125,51.75 246.125,51.75 250.125,51.75 252.125,51.75 254.125,51.75 256.125,51.75 258.125,51.75 260.125,51.75 262.375,51.75 264.125,51.75 271.75,63 273.75,63 275.75,63 277.75,63 279.75,63 272.75,64 274.75,64 276.75,64 278.75,64 280.75,64 271.75,65 273.75,65 275.75,65 277.75,65 279.75,65 272.75,66 274.75,66 276.75,66 278.75,66 280.75,66 282.75,66 284.75,66 288.75,66 290.75,66 271.75,67 273.75,67 275.75,67 277.75,67 279.75,67 272.75,68 274.75,68 276.75,68 278.75,68 280.75,68 271.75,69 273.75,69 275.75,69 277.75,69 279.75,69 272.75,70 274.75,70 276.75,70 278.75,70 280.75,70 271.75,71 273.75,71 275.75,71 277.75,71 279.75,71 245,71.5 247,71.5 249,71.5 251,71.5 215.5,72 217.5,72 219.5,72 221.5,72 223.5,72 225.5,72 227.5,72 229.5,72 254.75,72 256.75,72 258.75,72 260.75,72 262.75,72 264.75,72 266.75,72 268.75,72 270.75,72 272.75,72 274.75,72 276.75,72 278.75,72 280.75,72 244,72.5 246,72.5 250,72.5 252,72.5 214.5,73 216.5,73 218.5,73 220.5,73 222.5,73 224.5,73 253.75,73 255.75,73 257.75,73 263.75,73 265.75,73 267.75,73 269.75,73 271.75,73 273.75,73 275.75,73 277.75,73 279.75,73 245,73.5 251,73.5 215.5,74 217.5,74 219.5,74 221.5,74 223.5,74 254.75,74 256.75,74 258.75,74 262.75,74 264.75,74 266.75,74 268.75,74 270.75,74 272.75,74 274.75,74 276.75,74 278.75,74 280.75,74 232.5,74.5 234.5,74.5 238.5,74.5 240.5,74.5 244,74.5 246,74.5 250,74.5 252,74.5 214.5,75 216.5,75 218.5,75 220.5,75 222.5,75 224.5,75 226.5,75 228.5,75 230.5,75 242.25,75 253.75,75 255.75,75 257.75,75 263.75,75 265.75,75 267.75,75 269.75,75 271.75,75 273.75,75 275.75,75 277.75,75 279.75,75 215.5,76 217.5,76 219.5,76 221.5,76 223.5,76 225.5,76 227.5,76 229.5,76 231.5,76 233.5,76 239.375,76 241.25,76 243.25,76 245.125,76 250.875,76 252.75,76 254.75,76 256.75,76 258.75,76 262.75,76 264.75,76 266.75,76 268.75,76 270.75,76 272.75,76 274.75,76 276.75,76 278.75,76 280.75,76 214.5,77 216.5,77 218.5,77 220.5,77 222.5,77 224.5,77 226.5,77 228.5,77 230.5,77 232.5,77 234.5,77 238.5,77 240.25,77 242.25,77 244.125,77 246,77 250,77 251.75,77 253.75,77 255.75,77 257.75,77 263.75,77 265.75,77 267.75,77 269.75,77 271.75,77 273.75,77 275.75,77 277.75,77 279.75,77 215.5,78 217.5,78 219.5,78 221.5,78 223.5,78 225.5,78 227.5,78 229.5,78 231.5,78 233.5,78 235.5,78 237.5,78 239.375,78 241.25,78 243.25,78 245.125,78 247,78 249,78 250.875,78 252.75,78 254.75,78 256.75,78 258.75,78 262.75,78 264.75,78 266.75,78 268.75,78 270.75,78 272.75,78 274.75,78 276.75,78 278.75,78 280.75,78 282.75,78 284.75,78 288.75,78 290.75,78 214.5,79 216.5,79 218.5,79 220.5,79 222.5,79 224.5,79 226.5,79 228.5,79 230.5,79 232.5,79 234.5,79 236.5,79 238.5,79 240.25,79 242.25,79 244.125,79 246.125,79 248,79 250,79 251.75,79 253.75,79 255.75,79 257.75,79 259.75,79 261.75,79 263.75,79 265.75,79 267.75,79 269.75,79 271.75,79 273.75,79 275.75,79 277.75,79 279.75,79 281.75,79 283.75,79 285.75,79 287.75,79 289.75,79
